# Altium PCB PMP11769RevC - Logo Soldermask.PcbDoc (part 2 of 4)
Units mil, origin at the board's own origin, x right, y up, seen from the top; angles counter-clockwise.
Board outline 7800 x 8510 mil, 4 copper layers (Top, Inner Top, Inner Bottom, Bottom), stack 33.235 mil thick; 451 components, 226 nets, 1199 pads, 1742 vias.
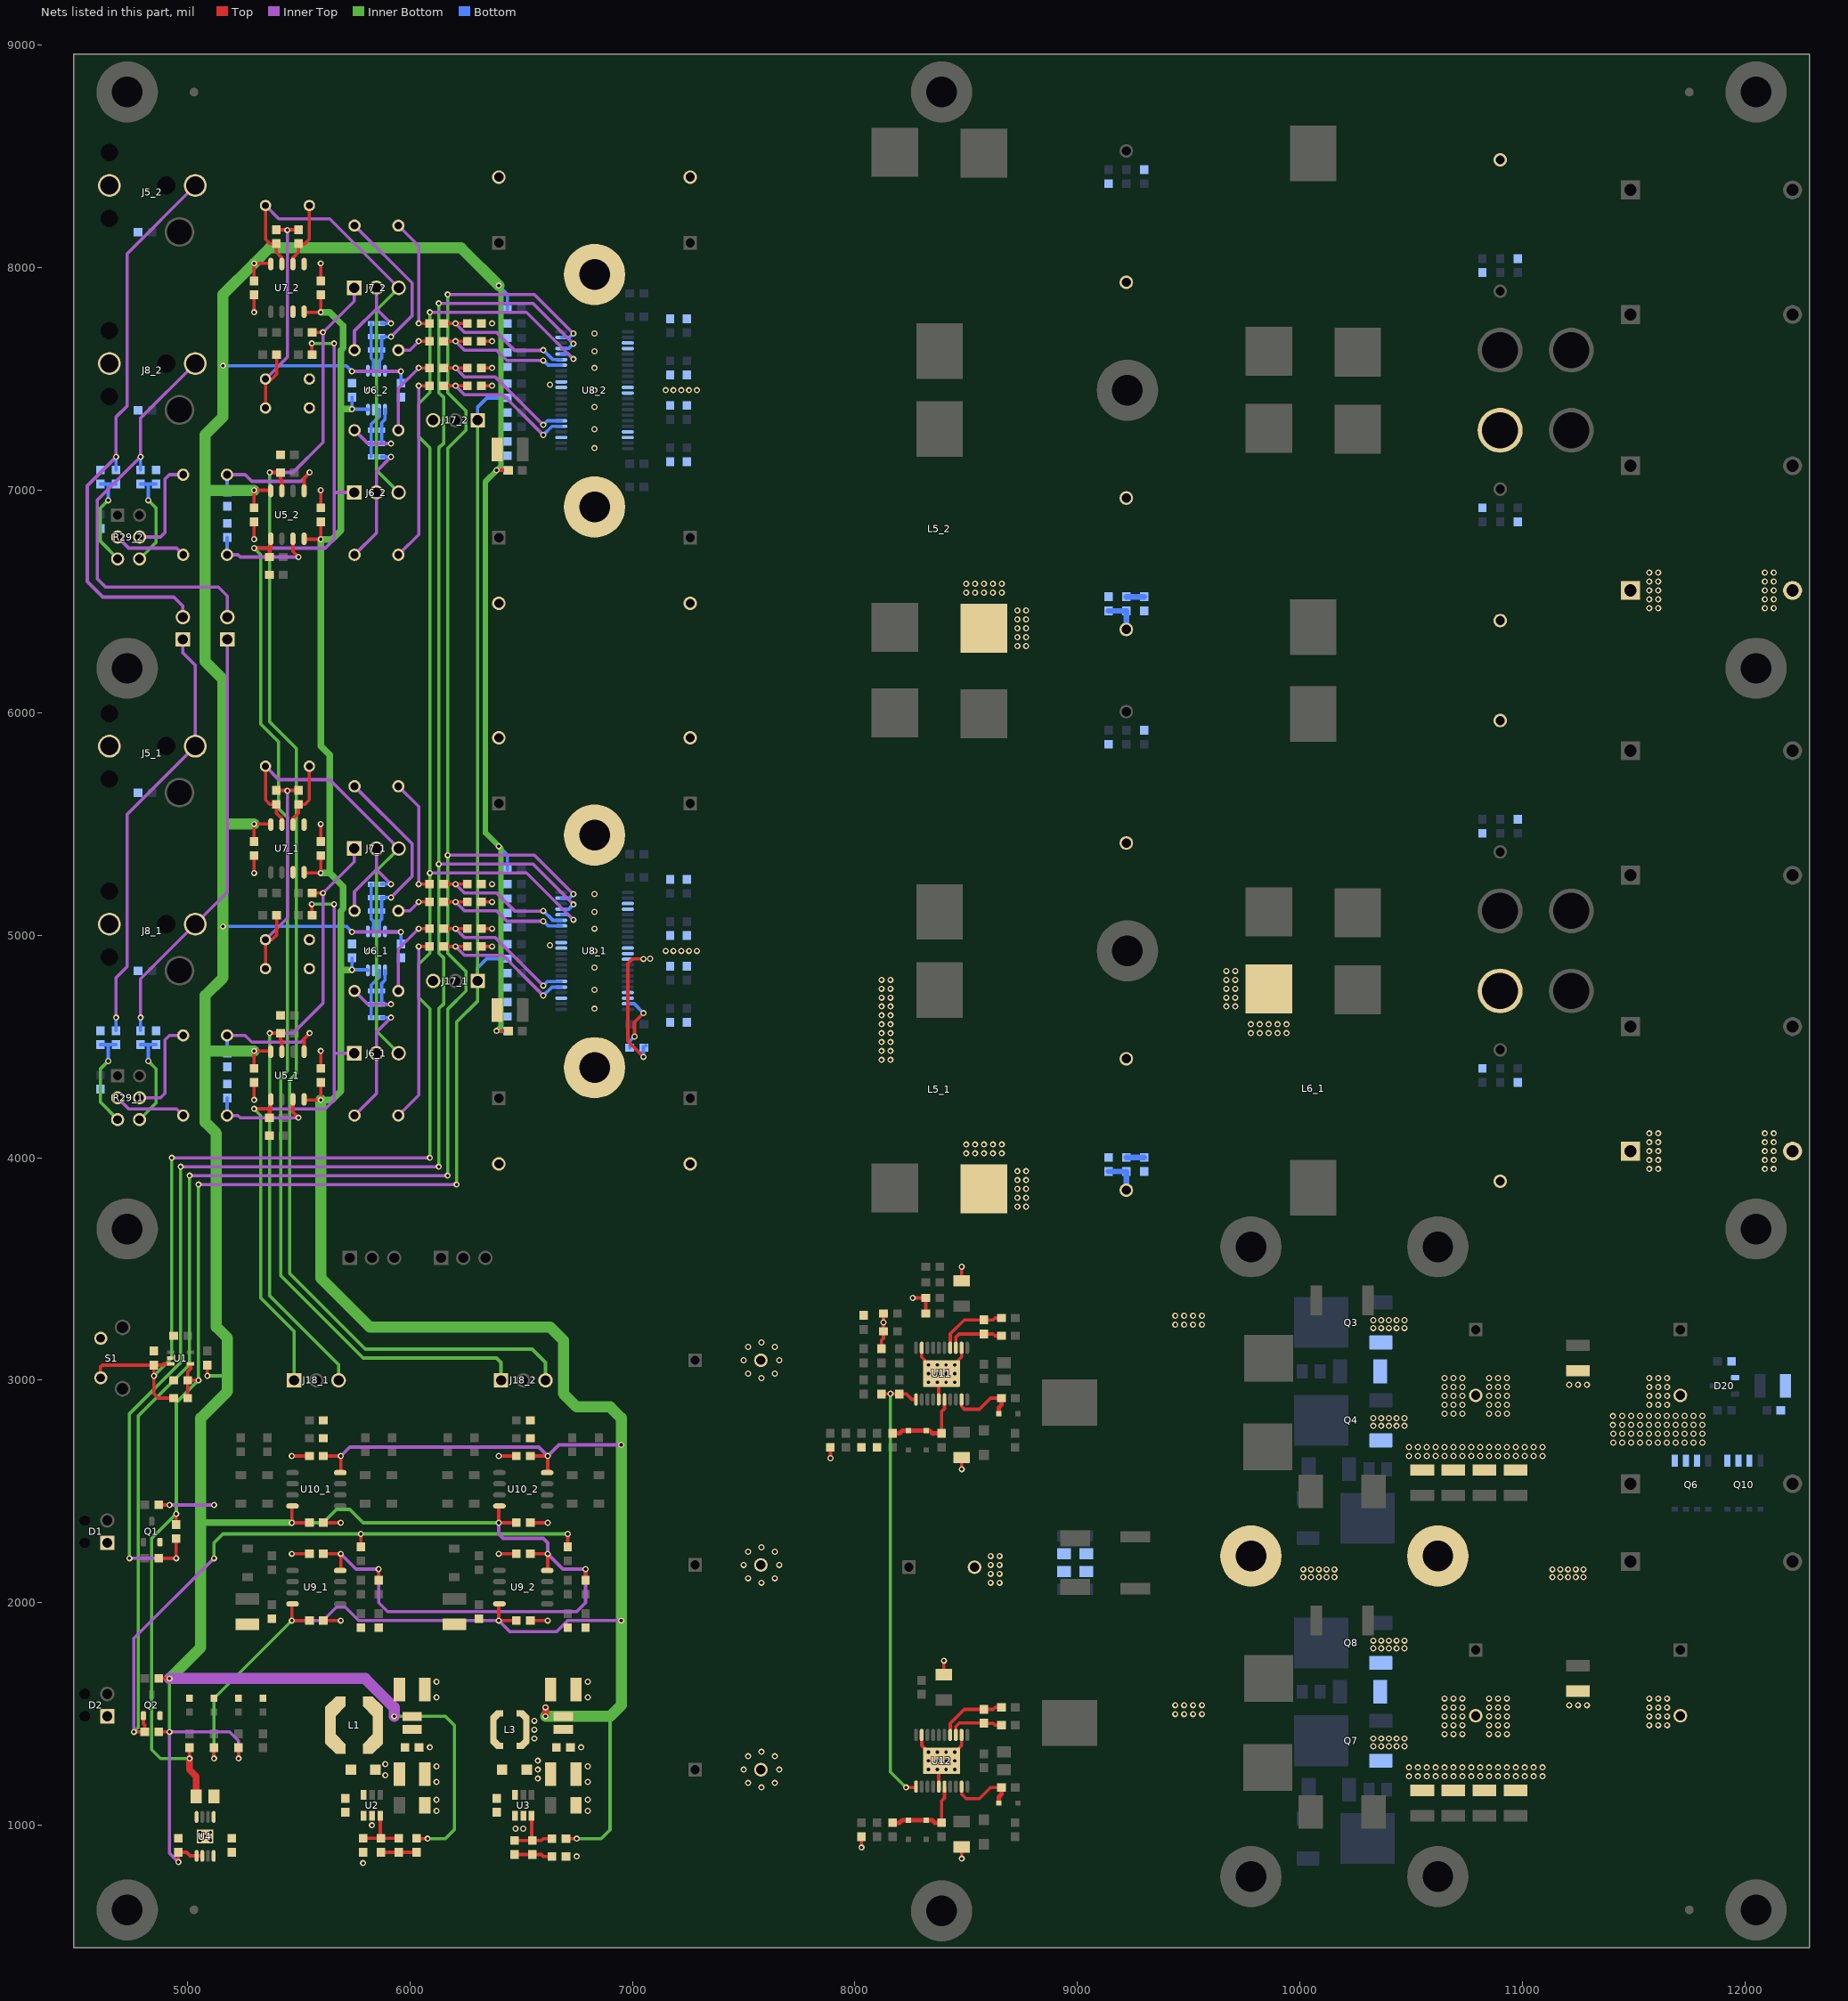
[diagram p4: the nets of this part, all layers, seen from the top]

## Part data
C1 C14 C58_1 C58_2 C59_1 C59_2 C71_1 C71_2: "CAP, CERM, 1 µF, 25 V, +/- 10%, X7R, 0603"
C2 C3 C7 C9 C12 C19_1 C19_2 C23_1 C23_2 C26_1 C26_2 C29_1 C29_2 C30_1 C30_2 C36_1 C36_2 C60_1 C60_2 C66_1 C66_2 C72_1 C72_2 C73_1 C73_2 C77_1 C77_2 C78_1 C78_2 C80_1 C80_2 C81_1 C81_2 C82_1 C82_2 C104 C106: "CAP, CERM, 0.1 µF, 50 V, +/- 10%, X7R, 0603"
C4 C13 C92 C93: "CAP, CERM, 1 µF, 50 V, +/- 10%, X7R, 1206"
C5 C6 C10 C11 C67_1 C67_2 C79_1 C79_2: "CAP, CERM, 10 µF, 25 V, +/- 20%, X7R, 1210"
C8 C17: "CAP, CERM, 220 pF, 50 V, +/- 5%, C0G/NP0, 0603"
C15: "CAP, CERM, 4.7 µF, 10 V, +/- 20%, X7R, 0805"
C16 C90: "CAP, CERM, 1000 pF, 50 V, +/- 10%, X7R, 0603"
C18_1 C18_2 C22_1 C22_2 C25_1 C25_2 C32_1 C32_2 C35_1 C35_2 C39_1 C39_2: "CAP, Film, 4.7 µF, 50 V, +/- 5%, TH"
C20_1 C20_2 C31_1 C31_2: "CAP, CERM, 22 pF, 50 V, +/- 5%, C0G/NP0, 0402"
C21_1 C21_2 C24_1 C24_2 C28_1 C28_2 C37_1 C37_2 C38_1 C38_2 C40_1 C40_2 C91: "CAP, CERM, 100 pF, 50 V, +/- 5%, C0G/NP0, 0603"
C27_1 C27_2: "CAP, Film, 0.1 µF, 63 V, +/- 5%, TH"
C33_1 C33_2: "CAP, Film, 0.22 µF, 63 V, +/- 5%, TH"
C34_1 C34_2: "CAP, Film, 0.15 µF, 63 V, +/- 5%, TH"
C41_1 C41_2 C61_1 C61_2 C68_1 C68_2 C74_1 C74_2: "CAP, CERM, 0.01 µF, 50 V, +/- 10%, X7R, 0603"
C42_1 C42_2 C43_1 C43_2 C44_1 C44_2 C45_1 C45_2 C109 C110 C113 C114: "CAP, AL, 820 µF, 50 V, +/- 20%, 0.042 ohm, TH"
C46_1 C46_2 C47_1 C47_2 C48_1 C48_2 C49_1 C49_2 C50_1 C50_2 C51_1 C51_2 C52_1 C52_2 C53_1 C53_2: "CAP, CERM, 1 µF, 50 V, +/- 10%, X7R, 0603"
C54_1 C54_2 C55_1 C55_2 C64_1 C64_2 C65_1 C65_2: "CAP, CERM, 0.033 µF, 50 V, +/- 10%, X7R, 0603"
C56_1 C56_2 C62_1 C62_2 C69_1 C69_2 C75_1 C75_2: "CAP, Film, 1 µF, 250 V, +/- 5%, TH"
C57_1 C57_2 C63_1 C63_2 C70_1 C70_2 C76_1 C76_2: "CAP, CERM, 1000 pF, 100 V, +/- 5%, C0G/NP0, 0603"
C83 C84: "CAP, CERM, 220 pF, 50 V, +/- 10%, X7R, 0603"
C85: "CAP, CERM, 0.047 µF, 50 V, +/- 10%, X7R, 0603"
C86 C87: "CAP, CERM, 4.7 µF, 16 V, +/- 20%, X7R, 1206"
C88 C89: "CAP, CERM, 0.22 µF, 25 V, +/- 10%, X7R, 0805"
C94: "CAP, CERM, 2.2 µF, 6.3 V, +/- 10%, X7R, AEC-Q200 Grade 1, 0603"
C95 C96 C111 C112 C115 C116: "CAP, CERM, 1000 pF, 100 V, +/- 20%, X7R, 0805"
C97 C99 C100 C102 C103 C105 C117 C119 C120 C122 C123: library part C3225X7R1H335M, "CAP, CERM, 4.7 µF, 50 V, +/- 15%, X7R, 1210"
C98 C101 C118 C121: "CAP, AL, 1800 µF, 35 V, +/- 20%, 0.028 ohm, TH"
C107 C108: "CAP, CERM, 0.1 µF, 100 V, +/- 10%, X7R, 0805"
D1 D2: library part 551-0403F, "LED, Yellow, TH"
D3 D8 D14 D15: library part PMEG6010CEH,115, "Diode, Schottky, 60 V, 1 A, SOD-123F"
D4 D5 D6 D7: "LED, Green, SMD"
D9_1 D9_2 D10_1 D10_2 D11_1 D11_2 D12_1 D12_2 D13_1 D13_2: library part 1N4148WFL-G3-08, "Diode, Switching, 100 V, 0.15 A, SOD-123FL"
D16 D21: library part SS36-E3/57T, "Diode, Schottky, 60 V, 3 A, SMC"
D17 D18 D19 D22 D23 D24: library part BAT54HT1G, "Diode, Schottky, 30 V, 0.2 A, SOD-323"
D20: "Diode, Zener, 15 V, 225 mW, SOT-23"
FID1 FID2 FID3 FID4: "Fiducial mark.  There is nothing to buy or mount."
J1 J3: "Header, 2.54 mm, 2x1, Gold, TH"
J2 J4 J6_1 J6_2 J7_1 J7_2 J17_1 J17_2 J18_1 J18_2: "Header, 2.54 mm, 3x1, Gold, TH"
J5_1 J5_2: "RCA Jack, Red, R/A, TH"
J8_1 J8_2: "RCA Jack, Black, R/A, TH"
J9_1 J9_2 J13_1 J13_2 J19: library part "973 582-101", "TEST SOCKET, PCB, 4MM, RED"
J10_1 J10_2 J11_1 J11_2 J14_1 J14_2 J15_1 J15_2: library part H3492-01, "Pin Receptacle, Dia 4 mm, Gold, TH"
J12_1 J12_2 J16_1 J16_2 J20: library part "973 582-100", "TEST SOCKET, PCB, 4MM, BLACK"
L1: "Inductor, Shielded Drum Core, Ferrite, 330 µH, 0.3 A, 1.2 ohm, SMD"
L2 L4: "Inductor, Shielded, Composite, 500 nH, 2.3 A, 0.04 ohm, SMD"
L3: "Inductor, Shielded Drum Core, Ferrite, 1 mH, 0.1 A, 21.5 ohm, SMD"
L5_1 L5_2 L6_1 L6_2 L7_1 L7_2 L8_1 L8_2 L9 L11: "Inductor, Shielded E Core, Ferrite, 10 µH, 28 A, 0.0026 ohm, SMD"
L10: library part IHLP2525AHERR10M01, "Inductor, Shielded, Ferrite, 100 nH, 18 A, 0.0035 ohm, SMD"
Q1 Q2: library part 2N7002E-T1-E3, "MOSFET, N-CH, 60 V, 0.24 A, SOT-23"
Q3 Q4 Q5 Q7 Q8 Q9: library part SUD50N10-18P, "MOSFET, N-CH, 60 V, 50 A, DPAK"
Q6 Q10: "MOSFET, N-CH, 30 V, 51 A, SON 5x6mm"
R1 R7: "RES, 47.5 k, 1%, 0.1 W, 0603"
R2 R8: "RES, 3.32 k, 1%, 0.1 W, 0603"
R3 R6 R25_1 R25_2 R30_1 R30_2 R43_1 R43_2 R53_1 R53_2 R55_1 R55_2 R56_1 R56_2 R59_1 R59_2 R61_1 R61_2 R63_1 R63_2 R64_1 R64_2 R65_1 R65_2 R66_1 R66_2: "RES, 10.0 k, 1%, 0.1 W, 0603"
R4 R19_1 R19_2 R20_1 R20_2 R26_1 R26_2 R36_1 R36_2 R37_1 R37_2 R42_1 R42_2: "RES, 100, 1%, 0.1 W, 0603"
R5: "RES, 80.6 k, 1%, 0.1 W, 0603"
R9 R17 R77: "RES, 49.9, 1%, 0.1 W, 0603"
R10 R16 R58_1 R58_2 R89 R91 R92 R100 R101: "RES, 1.00 k, 1%, 0.1 W, 0603"
R11 R18: "RES, 14.7 k, 1%, 0.1 W, 0603"
R12: "RES, 11.0 k, 1%, 0.1 W, 0603"
R13 R14: "RES, 2.94 k, 1%, 0.1 W, 0603"
R15: "RES, 200, 1%, 0.1 W, 0603"
R21_1 R21_2 R27_1 R27_2 R38_1 R38_2 R39_1 R39_2: "RES, 10.0 k, 1%, 0.063 W, 0402"
R22_1 R22_2: "RES, 13.7 k, 1%, 0.1 W, 0603"
R23_1 R23_2 R32_1 R32_2 R40_1 R40_2 R54_1 R54_2 R67 R70 R72 R73 R75 R76 R79 R83: "RES, 0, 5%, 0.1 W, 0603"
R24_1 R24_2 R41_1 R41_2 R74 R78: "RES, 100 k, 1%, 0.1 W, 0603"
R28_1 R28_2 R33_1 R33_2 R81 R84: "RES, 20.0 k, 1%, 0.1 W, 0603"
R29_1 R29_2: "Trimmer Potentiometer, 10K Ohm, 0.025W, TH"
R31_1 R31_2 R44_1 R44_2: "RES, 24.3 k, 1%, 0.1 W, 0603"
R34_1 R34_2: "RES, 4.53 k, 1%, 0.1 W, 0603"
R35_1 R35_2: "RES, 6.81 k, 1%, 0.1 W, 0603"
R45_1 R45_2 R46_1 R46_2 R47_1 R47_2 R48_1 R48_2 R50_1 R50_2 R51_1 R51_2 R52_1 R52_2 R69 R71: "RES, 3.32, 1%, 0.1 W, 0603"
R49_1 R49_2: "RES, 22.1 k, 1%, 0.1 W, 0603"
R57_1 R57_2: "RES, 23.7 k, 1%, 0.1 W, 0603"
R60_1 R60_2: "RES, 200 k, 1%, 0.1 W, 0603"
R62_1 R62_2: "RES, 365 k, 1%, 0.1 W, 0603"
R68: "RES, 30.1 k, 1%, 0.1 W, 0603"
R80: "RES, 7.68 k, 1%, 0.1 W, 0603"
R82: "RES, 37.4 k, 1%, 0.1 W, 0603"
R85: "RES, 3.74 k, 1%, 0.1 W, 0603"
R86: "RES, 44.2 k, 1%, 0.1 W, 0603"
R87 R90 R97 R99: "RES, 8.2, 5%, 0.75 W, 2010"
R88 R98: "RES, 0.0015, 1%, 1 W, 2512"
R93 R94 R95 R102 R103 R104: "RES, 4.75, 1%, 0.1 W, 0603"
R96: "RES, 0.68, 5%, 1 W, 2512"
S1: library part 1825027-2, "Switch, SPST-NO, Off-Mom, 0.05 A, 12 V, R/A, TH"
U1: library part TPS3803-01QDCKRQ1, "VOLTAGE DETECTOR, DCK0005A"
U2 U3: library part LM2841XMK-ADJL, "300 mA/600 mA up to 42V Input Step-Down DC/DC Regulator, 6-pin Tiny SOT23"
U4: library part TPS7A6633QDGNRQ1, "High-Voltage Ultralow-Iq Low-Dropout Regulator, DGN0008D"
U5_1 U5_2 U7_1 U7_2: library part OPA1662AIDRQ1, "Automotive Catalog, Sound Plus, Low-Power, Low-Noise and Distortion, Audio Operational Amplifier, 3 to 36 V, -40 to 85 degC, 8-pin SOIC (D0008A), Green (RoHS & no Sb/Br)"
U6_1 U6_2: "Automotive Catalog, Sound Plus, Low-Power, Low-Noise and Distortion, Audio Operational Amplifier, 3 to 36 V, -40 to 85 degC, 8-pin SOP (DGK0008A), Green (RoHS & no Sb/Br)"
U8_1 U8_2: library part TPA3251D2DDVR, "150W Stereo/300W MONO PurePath HD Analog-input Power Stage, DDV0044D"
U9_1 U9_2 U10_1 U10_2: library part LM2904QDRQ1, "Automotive Dual Low Power Op Amp, D0008A"
U11 U12: library part LM5122QMHX/NOPB, "Wide Input Synchronous Boost Controller with Multiple Phase Capability, PWP0020A"

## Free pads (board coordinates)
  round 275.59 hole 137.8 unplated: 0(4730,620) 0(4730,3680) 0(4730,6200) 0(4730,8790) 0(8390,615) 0(8390,8790) 0(9225,4930) 0(9225,7450) 0(9780,770) 0(9780,3600) 0(10620,770) 0(10620,3600) 0(12050,620) 0(12050,3680) 0(12050,6200) 0(12050,8790)
  round 275.59 hole 137.8: 0(6830,4405) 0(6830,5450) 0(6830,6925) 0(6830,7970) 0(9780,2210) 0(10620,2210)

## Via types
v1: diameter 28, hole 15, Top to Bottom, 1742 vias

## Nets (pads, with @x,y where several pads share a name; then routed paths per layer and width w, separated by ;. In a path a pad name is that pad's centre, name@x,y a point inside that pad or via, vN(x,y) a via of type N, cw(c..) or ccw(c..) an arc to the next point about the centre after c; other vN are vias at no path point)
+3V3: C2.2 C15.1 J17_1.1 J17_2.1 R1.2 R3.2 R15.2 R54_1.1 R54_2.1 U1.4 U4.8 | length 8355.1
  Top w15: R1.2@4950,2351.5 v1(4950,2400) ; R3.2@5001.5,2920 C2.2@5001.5,3000 ; v1(5010,1300) R15.2@5010,1348.5 ; U1.4@5014.29,3074.41 5014.29,3051.14 5001.5,3038.35 C2.2@5001.5,3000 ; v1(5050,3000) C2.2@5001.5,3000
  Top w30: v1(5010,1300) 5010,1250 5040,1220 C15.1@5040,1130
  Inner Top w15: v1(5050,3880) v1(6210,3880)
  Inner Bottom w15: v1(5010,1300) 4880,1300 4840,1340 4840,2290 v1(4950,2400) 4950.37,2400.37 4950.37,2900.37 v1(5050,3000) v1(5050,3880) ; v1(6210,3880) 6210,4610 6305,4705 J17_1.1@6305,4795 J17_2.1@6305,7315
  Bottom w15: J17_1.1@6305,4795 6305,4854.49 6345.51,4895 R54_1.1@6438.5,4895 ; J17_2.1@6305,7315 6305,7374.49 6345.51,7415 R54_2.1@6438.5,7415
+12V: C6.1 C14.1 C23_1.1 C23_2.1 C26_1.1 C26_2.1 C29_1.1 C29_2.1 C77_1.1 C77_2.1 C78_1.1 C78_2.1 L2.2 R2.2 R5.2 R7.2 R8.2 R9.2 R13.2 R46_1.2 R46_2.2 R48_1.2 R48_2.2 R51_1.2 R51_2.2 R57_1.2 R57_2.2 U4.1 U4.2 U5_1.8 U5_2.8 U6_1.8 U6_2.8 U7_1.8 U7_2.8 U9_1.8 U9_2.8 U10_1.8 U10_2.8 | length 22962.4
  Top w15: R7.2@4871.5,1420 v1(4920,1420) ; R8.2@4871.5,1660 v1(4920,1660) ; R2.2@4871.5,2440 v1(4920,2440) ; v1(4960,835) C14.1@4960,878.5 4996.5,878.5 5012.6,862.4 U4.1@5041.61,862.4 U4.2@5067.2,862.4 ; v1(5090,3020) R5.2@5090,3068.5 ; v1(5230,1300) R13.2@5230,1348.5 ; C26_1.1@5300,4401.5 v1(5300,4480) 5372.28,4480 U5_1.8@5375,4477.28 ; C29_1.1@5300,5421.5 v1(5300,5500) 5372.28,5500 U7_1.8@5375,5497.28 ; C26_2.1@5300,6921.5 v1(5300,7000) 5372.28,7000 U5_2.8@5375,6997.28 ; C29_2.1@5300,7941.5 v1(5300,8020) 5372.28,8020 U7_2.8@5375,8017.28 ; U10_1.8@5472.72,2435 5470,2432.28 v1(5470,2360) C78_1.1@5548.5,2360 ; C77_1.1@5611.5,2220 v1(5690,2220) 5690,2147.72 U9_1.8@5687.28,2145 ; R57_1.2@5860,2101.5 v1(5860,2151.67) ; R9.2@6030,941.5 6031.5,940 v1(6080,940) ; v1(6390,4570) R48_1.2@6443.5,4570 ; v1(6390,7090) R48_2.2@6443.5,7090 ; U10_2.8@6402.72,2435 6400,2432.28 v1(6400,2360) C78_2.1@6478.5,2360 ; C77_2.1@6541.5,2220 v1(6620,2220) 6620,2147.72 U9_2.8@6617.28,2145 ; R57_2.2@6790,2101.5 v1(6790,2151.67)
  Inner Top w15: v1(4920,2440) v1(5120,2440) ; v1(4960,835) 4920,875 v1(4920,1420) 5190,1420 5230,1380 v1(5230,1300) ; v1(5690,2220) 5758.33,2151.67 v1(5860,2151.67) 5860,2000 5900,1960 6750,1960 6790,2000 v1(6790,2151.67) 6688.33,2151.67 v1(6620,2220) 6620,2270 6600,2290 6420,2290 6400,2310 v1(6400,2360) ; v1(5740,5015) v1(5960,5015) ; v1(5740,7535) v1(5960,7535)
  Inner Top w50: v1(4920,1660) 5800,1660 5930,1530 v1(5930,1490)
  Inner Bottom w15: v1(4920,1420) v1(4920,1660) ; 5060,2440 v1(5120,2440) ; v1(5090,3020) 5170,3020 5180,3030 ; v1(5470,2360) 5610,2360 5670,2420 5730,2420 5790,2360 v1(6400,2360) ; v1(5930,1490) 6160,1490 6200,1450 6200,980 6160,940 v1(6080,940)
  Inner Bottom w25: v1(6390,4570) 6410.02,4590.02 6410.02,5389.98 v1(6400,5400) 6340,5460 6339.63,5460 6339.63,7039.63 v1(6390,7090) 6410.02,7110.02 6410.02,7909.98 v1(6400,7920)
  Inner Bottom w30: 5060,2360 v1(5470,2360)
  Inner Bottom w50: v1(4920,1660) 5060,1800 5060,2360 5060,2440 5060,2830 5180,2950 5180,3030 5180,3190 5130,3240 5130,4110 5080,4160 5080,4480 ; v1(5300,4480) 5080,4480 ; v1(5300,5500) 5160,5500 ; v1(5300,7000) 5080,7000 ; v1(6400,7920) 6230,8090 5370,8090 v1(5300,8020) 5160,7880 v1(5160,7560) 5160,7330 5080,7250 5080,7000 ; 5080,4480 5080,4730 5160,4810 5160,5500 ; 5080,7000 5080,6230 5160,6150 5160,5500
  Bottom w15: v1(5160,5040) 5715,5040 v1(5740,5015) ; v1(5160,7560) 5715,7560 v1(5740,7535) ; U6_1.8@5888.39,5017.6 5890.98,5015 v1(5960,5015) C23_1.1@5960,4961.5 ; U6_2.8@5888.39,7537.6 5890.98,7535 v1(5960,7535) C23_2.1@5960,7481.5 ; v1(6390,4570) R46_1.2@6438.5,4570 ; v1(6390,7090) R46_2.2@6438.5,7090 ; v1(6400,5400) 6438.5,5361.5 R51_1.2@6438.5,5295 ; v1(6400,7920) 6438.5,7881.5 R51_2.2@6438.5,7815
-12V: C11.2 C19_1.1 C19_2.1 C30_1.1 C30_2.1 C36_1.1 C36_2.1 C80_1.1 C80_2.1 C82_1.1 C82_2.1 L4.2 R14.2 R16.2 U5_1.4 U5_2.4 U6_1.4 U6_2.4 U7_1.4 U7_2.4 U9_1.4 U9_2.4 U10_1.4 U10_2.4 | length 14081.9
  Top w15: v1(5120,1300) R14.2@5120,1348.5 ; U9_1.4@5472.72,1995 5470,1992.28 v1(5470,1920) C80_1.1@5548.5,1920 ; U5_1.4@5525,4262.72 5527.72,4260 v1(5600,4260) C19_1.1@5600,4338.5 ; U7_1.4@5525,5282.72 5527.72,5280 v1(5600,5280) C36_1.1@5600,5358.5 ; U5_2.4@5525,6782.72 5527.72,6780 v1(5600,6780) C19_2.1@5600,6858.5 ; U7_2.4@5525,7802.72 5527.72,7800 v1(5600,7800) C36_2.1@5600,7878.5 ; C82_1.1@5611.5,2660 v1(5690,2660) 5690,2587.72 U10_1.4@5687.28,2585 ; U9_2.4@6402.72,1995 6400,1992.28 v1(6400,1920) C80_2.1@6478.5,1920 ; C82_2.1@6541.5,2660 v1(6620,2660) 6620,2587.72 U10_2.4@6617.28,2585 ; R16.2@6701.5,940 v1(6750,940)
  Top w30: v1(6610,1490) v1(6610,1530)
  Inner Top w15: v1(5470,1920) 5610,1920 5670,1980 5710,1980 5770,1920 v1(6400,1920) 6450,1870 6660,1870 6710,1920 v1(6950,1920) ; v1(5690,2660) 5730,2700 6580,2700 v1(6620,2660) 6670,2710 v1(6950,2710)
  Inner Bottom w15: v1(5120,1300) 5120,1570 v1(5470,1920) ; v1(6750,940) 6860,940 6900,980 6900,1485 6895,1490
  Inner Bottom w30: v1(5600,4260) 5650,4260 5690,4300 5690,4845 ; v1(5600,5280) 5640,5280 ; v1(5600,7800) 5640,7800 5701.14,7738.86 5701.14,7640 5690,7628.86 5690,7365 ; v1(5740,4845) 5690,4845 ; v1(5740,7365) 5690,7365 ; 5640,5280 5701.14,5218.86 5701.14,5120 5690,5108.86 5690,4845 ; 5640,5280 5640,5810 5600,5850 v1(5600,6780) 5650,6780 5690,6820 5690,7365
  Inner Bottom w50: v1(5600,4260) 5600,3460 5820,3240 6630,3240 6690,3180 6690,2940 6750,2880 6900,2880 6950,2830 v1(6950,2710) v1(6950,1920) 6950,1540 6900,1490 ; v1(6610,1490) 6895,1490
  Bottom w15: C30_1.1@5740,4898.5 v1(5740,4845) 5809.02,4845 U6_1.4@5811.61,4842.4 ; C30_2.1@5740,7418.5 v1(5740,7365) 5809.02,7365 U6_2.4@5811.61,7362.4
/CLIP_1: Q2.1 R7.1 R58_1.2 R58_2.2 U8_1.21 U8_2.21 | length 12109.8
  Top w15: v1(4760,1420) R7.1@4808.5,1420 4808.5,1451.5 4802.6,1457.4 Q2.1@4802.6,1492.76 Q2.1@4799.84,1490 ; R58_1.2@5780,2251.5 v1(5780,2310) ; R58_2.2@6710,2251.5 v1(6710,2310)
  Inner Top w15: v1(4760,1420) 4760,1840 v1(5120,2200) ; v1(5010,3920) v1(6170,3920) ; v1(6170,5360) 6560,5360 v1(6735,5185) ; v1(6170,7880) 6560,7880 v1(6735,7705)
  Inner Bottom w15: v1(4760,1420) 4780,1440 4780,2840 5010,3070 v1(5010,3920) ; v1(5120,2200) 5120,2270 5160,2310 v1(5780,2310) v1(6710,2310) ; v1(6170,3920) 6170,4667.15 6252.85,4750 6252.85,4837.15 6170,4920 v1(6170,5360) 6170,7187.15 6252.85,7270 6252.85,7357.15 6170,7440 v1(6170,7880)
  Bottom w15: U8_1.21@6680.39,5167.5 6717.5,5167.5 v1(6735,5185) ; U8_2.21@6680.39,7687.5 6717.5,7687.5 v1(6735,7705)
/FAULT_1: R1.1 R4.1 U8_1.19 U8_2.19 | length 8797.1
  Top w15: R4.1@4871.5,2200 v1(4950,2200) R1.1@4950,2288.5
  Inner Top w15: v1(4740,2200) v1(4950,2200) ; v1(4970,3960) v1(6130,3960) ; v1(6130,5320) 6553.7,5320 v1(6735,5138.7) ; v1(6130,7840) 6553.7,7840 v1(6735,7658.7)
  Inner Bottom w15: v1(4740,2200) 4740,2850 4970,3080 v1(4970,3960) ; v1(6130,3960) 6130,4670 6152.85,4692.85 6152.85,4897.15 6130,4920 v1(6130,5320) 6130,7190 6152.85,7212.85 6152.85,7417.15 6130,7440 v1(6130,7840)
  Bottom w15: U8_1.19@6680.39,5117.5 6713.8,5117.5 v1(6735,5138.7) ; U8_2.19@6680.39,7637.5 6713.8,7637.5 v1(6735,7658.7)
/RESET_1: C1.1 R3.1 S1.2 U1.3 U8_1.18 U8_2.18 | length 8243.8
  Top w15: S1.2@4610.98,3011.42 4610,3012.4 4610,3060 4618.5,3068.5 C1.1@4850,3068.5 ; U1.3@4925.71,3074.41 4894.41,3074.41 4888.5,3068.5 C1.1@4850,3068.5 ; R3.1@4938.5,2920 4870,2920 4850,2940 v1(4850,3020) C1.1@4850,3068.5
  Inner Top w15: v1(4930,4000) v1(6090,4000) ; v1(6090,5280) 6525,5280 v1(6735,5070) ; v1(6090,7800) 6525,7800 v1(6735,7590)
  Inner Bottom w15: v1(4850,3020) 4930,3100 v1(4930,4000) ; v1(6090,4000) 6090,4670 6040,4720 6040,4870 6090,4920 v1(6090,5280) 6090,7190 6040,7240 6040,7390 6090,7440 v1(6090,7800)
  Bottom w15: U8_1.18@6680.39,5092.5 6712.5,5092.5 v1(6735,5070) ; U8_2.18@6680.39,7612.5 6712.5,7612.5 v1(6735,7590)
BUFF_L1: J6_1.1 J18_1.1 R28_1.1 R31_1.2 U5_1.1 | length 2958.1
  Top w15: v1(5300,4220) 5370,4220 5375,4215 ; R31_1.2@5368.5,4180 5368.5,4208.5 5375,4215 ; U5_1.1@5372.28,4260 U5_1.1@5375,4262.72 5375,4215 ; v1(5560,5140) 5560,5091.5 R28_1.1@5561.5,5090
  Inner Top w15: v1(5300,4220) 5620,4220 5660,4260 5660,4470 ; v1(5660,5140) 5660,4470 ; J6_1.1@5750,4470 5660,4470
  Inner Bottom w15: v1(5300,4220) 5330,4190 5330,3370 5480,3220 J18_1.1@5480,3000 ; v1(5560,5140) v1(5660,5140)
BUFF_L2: J6_2.1 J18_2.1 R28_2.1 R31_2.2 U5_2.1 | length 6239.6
  Top w15: v1(5300,6740) 5370,6740 5375,6735 ; R31_2.2@5368.5,6700 5368.5,6728.5 5375,6735 ; U5_2.1@5372.28,6780 U5_2.1@5375,6782.72 5375,6735 ; v1(5560,7660) 5560,7611.5 R28_2.1@5561.5,7610
  Inner Top w15: v1(5300,6740) 5620,6740 5660,6780 5660,6990 ; v1(5660,7660) 5660,6990 ; J6_2.1@5750,6990 5660,6990
  Inner Bottom w15: v1(5300,6740) 5330,6710 5330,5950 5410,5870 5410,5570 5450,5530 5450,4390 5420,4360 5420,3470 5790,3100 6390,3100 6410,3080 J18_2.1@6410,3000 ; v1(5560,7660) v1(5660,7660)
BUFF_R1: J7_1.1 J18_1.3 R33_1.1 R44_1.2 U5_1.7 | length 2919.4
  Top w15: v1(5370,4560) R44_1.2@5418.5,4560 5418.5,4531.5 5425,4525 U5_1.7@5425,4477.28 ; R33_1.1@5561.5,5190 v1(5610,5190)
  Inner Top w15: v1(5370,4560) 5474.45,4560 5610,4695.55 v1(5610,5190) 5750,5330 J7_1.1@5750,5390
  Inner Bottom w15: v1(5370,4560) 5370,3380 5680,3070 J18_1.3@5680,3000
BUFF_R2: J7_2.1 J18_2.3 R33_2.1 R44_2.2 U5_2.7 | length 6288.8
  Top w15: v1(5370,7080) R44_2.2@5418.5,7080 5418.5,7051.5 5425,7045 U5_2.7@5425,6997.28 ; R33_2.1@5561.5,7710 v1(5610,7710)
  Inner Top w15: v1(5370,7080) 5474.45,7080 5610,7215.55 v1(5610,7710) 5750,7850 J7_2.1@5750,7910
  Inner Bottom w15: v1(5370,7080) 5370,5960 5490,5840 5490,4380 5460,4350 5460,3480 5800,3140 6550,3140 6610,3080 J18_2.3@6610,3000
COMP: C85.1 C90.1 U11.11 U12.11 | length 2010.5
  Top w15: C90.1@8120,2938.5 C85.1@8200,2938.5 8231.5,2938.5 8256.14,2913.86 U11.11@8274.84,2913.86 ; v1(8230,1170) 8270.98,1170 U12.11@8274.84,1173.86
  Inner Bottom w15: v1(8160,2940) 8160,1240 v1(8230,1170)
CSN-1: C83.2 R92.1 U11.3 | length 262.2
  Top w15: U11.3@8453.98,3146.14 8453.98,3193.35 8453.66,3193.66 8468.5,3208.5 C83.2@8580,3208.5 8621.5,3208.5 8630,3200 R92.1@8658.5,3200
CSN-2: C84.2 R101.1 U12.3 | length 253.1
  Top w15: U12.3@8453.98,1406.14 8453.98,1443.98 8470,1460 8578.5,1460 C84.2@8580,1458.5 8621.5,1458.5 8630,1450 R101.1@8658.5,1450
CSP-1: C83.1 R91.1 U11.4 | length 322.3
  Top w15: U11.4@8428.39,3146.14 8428.39,3207.76 8428.07,3208.07 8491.5,3271.5 C83.1@8580,3271.5 8621.5,3271.5 8630,3280 R91.1@8658.5,3280
CSP-2: C84.1 R100.1 U12.4 | length 312
  Top w15: U12.4@8428.39,1406.14 8428.39,1458.39 8491.5,1521.5 C84.1@8580,1521.5 8621.5,1521.5 8630,1530 R100.1@8658.5,1530
GND: C1.2 C2.1 C4.2 C5.2 C6.2 C7.1 C10.1 C11.1 C12.2 C13.2 C14.2 C15.2 C16.2 C19_1.2 C19_2.2 C21_1.2 C21_2.2 C23_1.2 C23_2.2 C24_1.2 C24_2.2 C26_1.2 C26_2.2 C28_1.2 C28_2.2 C29_1.2 C29_2.2 C30_1.2 C30_2.2 C33_1.2 C33_2.2 C34_1.2 C34_2.2 C36_1.2 C36_2.2 C37_1.2 C37_2.2 C38_1.2 C38_2.2 C40_1.2 C40_2.2 C42_1.2 C42_2.2 C43_1.2 C43_2.2 C44_1.2 C44_2.2 C45_1.2 C45_2.2 C46_1.2 C46_2.2 C47_1.2 C47_2.2 C48_1.2 C48_2.2 C49_1.2 C49_2.2 C50_1.2 C50_2.2 C51_1.2 C51_2.2 C52_1.2 C52_2.2 C53_1.2 C53_2.2 C56_1.2 C56_2.2 C57_1.2 C57_2.2 C58_1.2 C58_2.2 C59_1.2 C59_2.2 C60_1.1 C60_2.1 C62_1.2 C62_2.2 C63_1.2 C63_2.2 C66_1.1 C66_2.1 C67_1.2 C67_2.2 C69_1.2 C69_2.2 C70_1.2 C70_2.2 C71_1.1 C71_2.1 C72_1.1 C72_2.1 C73_1.2 C73_2.2 C75_1.2 C75_2.2 C76_1.2 C76_2.2 C77_1.2 C77_2.2 C78_1.2 C78_2.2 C79_1.2 C79_2.2 C80_1.2 C80_2.2 C81_1.1 C81_2.1 C82_1.2 C82_2.2 C86.2 C87.2 C91.2 C92.1 C93.1 C94.2 C97.2 C98.2 C99.2 C100.2 C101.2 C102.2 C103.2 C104.2 C105.2 C106.1 C107.1 C108.2 C109.2 C110.2 C112.2 C113.2 C114.2 C115.1 C117.2 C118.2 C119.2 C120.2 C121.2 C122.2 C123.2 D1.1 D2.1 D3.2 D4.1 D5.1 D6.2 D7.1 D20.1 J5_1.1 J5_2.1 J8_1.1 J8_2.1 J17_1.3 J17_2.3 L3.2 pad.0@6830,4405 pad.0@6830,5450 pad.0@6830,6925 pad.0@6830,7970 pad.0@9780,2210 pad.0@10620,2210 Q1.2 Q2.2 Q3.3 Q4.3 Q6.1 Q6.2 Q6.3 Q7.3 Q8.3 Q10.1 Q10.2 Q10.3 R6.1 R10.1 R17.1 R23_1.1 R23_2.1 R24_1.1 R24_2.1 R30_1.2 R30_2.2 R32_1.1 R32_2.1 R40_1.1 R40_2.1 R41_1.1 R41_2.1 R43_1.2 R43_2.2 R45_1.1 R45_2.1 R47_1.1 R47_2.1 R49_1.1 R49_2.1 R50_1.1 R50_2.1 R52_1.1 R52_2.1 R53_1.1 R53_2.1 R60_1.1 R60_2.1 R61_1.2 R61_2.2 R65_1.1 R65_2.1 R66_1.1 R66_2.1 R79.2 R80.1 R81.1 R82.1 R83.1 R84.1 R85.1 R86.1 R90.1 R99.1 S1.1 U1.2 U2.2 U4.5 U4.9 U6_1.3 U6_1.5 U6_2.3 U6_2.5 U7_1.3 U7_1.5 U7_2.3 U7_2.5 U8_1.3 U8_1.12 U8_1.13 U8_1.25 U8_1.26 U8_1.33 U8_1.34 U8_1.41 U8_1.42 U8_2.3 U8_2.12 U8_2.13 U8_2.25 U8_2.26 U8_2.33 U8_2.34 U8_2.41 U8_2.42 U11.2 U11.9 U11.15 U11.21 U12.2 U12.9 U12.15 U12.21 | length 3077.5
  Top w15: v1(5300,4260) C26_1.2@5300,4338.5 ; v1(5300,5280) C29_1.2@5300,5358.5 ; v1(5300,6780) C26_2.2@5300,6858.5 ; v1(5300,7800) C29_2.2@5300,7878.5 ; v1(5470,2220) C77_1.2@5548.5,2220 ; v1(5470,2660) C82_1.2@5548.5,2660 ; C19_1.2@5600,4401.5 v1(5600,4480) ; C36_1.2@5600,5421.5 v1(5600,5500) ; C19_2.2@5600,6921.5 v1(5600,7000) ; C36_2.2@5600,7941.5 v1(5600,8020) ; C80_1.2@5611.5,1920 v1(5690,1920) ; C78_1.2@5611.5,2360 v1(5690,2360) ; C21_1.2@6321.5,4948.7 6322.8,4950 v1(6370,4950) ; C28_1.2@6321.5,5028.7 6322.8,5030 v1(6370,5030) ; C40_1.2@6321.5,5148.7 6322.8,5150 v1(6370,5150) ; C21_2.2@6321.5,7468.7 6322.8,7470 v1(6370,7470) ; C28_2.2@6321.5,7548.7 6322.8,7550 v1(6370,7550) ; C40_2.2@6321.5,7668.7 6322.8,7670 v1(6370,7670) ; v1(6400,2220) C77_2.2@6478.5,2220 ; v1(6400,2660) C82_2.2@6478.5,2660 ; C80_2.2@6541.5,1920 v1(6620,1920) ; C78_2.2@6541.5,2360 v1(6620,2360) ; v1@7890,2651.5 R81.1@7890,2700 ; v1(8030,900) R84.1@8030,948.5 ; R85.1@8120,3141.5 8120,3180 8128.5,3188.5 v1(8128.5,3260) C94.2@8128.5,3300 ; v1(8260,3370) R80.1@8318.5,3370 C91.2@8318.5,3300 ; U11.9@8300.12,3155.51 8300,3155.39 8300,3105 8365.63,3039.37 U11.21@8389.68,3039.37 ; U12.9@8300.43,1406.14 8300.43,1359.57 8370,1290 v1(8370.32,1290) U12.21@8390,1290 ; U11.15@8376.89,2923.23 8376.89,3026.57 U11.21@8389.68,3039.37 ; U12.15@8377.2,1173.86 8377.2,1277.2 U12.21@8390,1290 ; C93.1@8400,1677.09 v1(8400,1740) ; U11.2@8479.25,3155.51 8480,3154.76 8480,3105 8414.37,3039.37 U11.21@8389.68,3039.37 ; U12.2@8479.57,1406.14 8479.57,1359.57 8410,1290 v1(8409.69,1290) U12.21@8390,1290 ; v1(8480,850) C87.2@8480,902.91 ; v1(8480,2600.55) C86.2@8480,2652.91 ; C92.1@8480,3447.09 v1(8480,3510)
  other v1: 5790,830 6750,860 5056.38,932.28 5103.62,932.28 5080,950 5056.38,967.72 5103.62,967.72 5830,1000 6120,1065 6800,1065 6120,1115 6800,1115 7580,1170 7520,1190 7640,1190 6120,1195 6800,1195 10490,1220 10530,1220 10570,1220 10610,1220 10650,1220 10690,1220 10730,1220 10770,1220 10810,1220 10850,1220 10890,1220 10930,1220 10970,1220 11010,1220 11050,1220 11090,1220 5890,1225 7500,1250 7660,1250 8330.94,1250.63 8370.32,1250.63 8409.69,1250.63 8449.06,1250.63 10490,1260 10530,1260 10570,1260 10610,1260 10650,1260 10690,1260 10730,1260 10770,1260 10810,1260 10850,1260 10890,1260 10930,1260 10970,1260 11010,1260 11050,1260 11090,1260 6120,1265 6800,1265 5890,1275 8330.94,1290 8449.06,1290 7520,1310 7640,1310 8330.94,1329.37 8370.32,1329.37 8409.69,1329.37 8449.06,1329.37 7580,1330 6090,1350 6770,1350 10330,1355 10365,1355 10400,1355 10435,1355 10470,1355 6560,1390 10330,1390 10365,1390 10400,1390 10435,1390 10470,1390 10650,1410 10690,1410 10730,1410 10850,1410 10890,1410 10930,1410 6560,1430 10650,1450 10690,1450 10730,1450 10850,1450 10890,1450 10930,1450 11570,1450 11610,1450 11650,1450 6560,1470 10650,1490 10690,1490 10730,1490 10850,1490 10890,1490 10930,1490 11570,1490 11610,1490 11650,1490 9440,1500 9480,1500 9520,1500 9560,1500 10650,1530 10690,1530 10730,1530 10850,1530 10890,1530 10930,1530 11570,1530 11610,1530 11650,1530 9440,1540 9480,1540 9520,1540 9560,1540 11210,1540 11250,1540 11290,1540 10650,1570 10690,1570 10730,1570 10850,1570 10890,1570 10930,1570 11570,1570 11610,1570 11650,1570 6120,1575 6800,1575 6120,1645 6800,1645 10330,1795 10365,1795 10400,1795 10435,1795 10470,1795 10330,1830 10365,1830 10400,1830 10435,1830 10470,1830 7580,2090 8610,2090 8650,2090 7520,2110 7640,2110 10015,2115 10050,2115 10085,2115 10120,2115 10155,2115 11135,2115 11170,2115 11205,2115 11240,2115 11275,2115 8610,2130 8650,2130 10015,2150 10050,2150 10085,2150 10120,2150 10155,2150 11135,2150 11170,2150 11205,2150 11240,2150 11275,2150 7500,2170 7660,2170 8610,2170 8650,2170 8610,2210 8650,2210 7520,2230 7640,2230 7580,2250 7890,2650 10490,2660 10530,2660 10570,2660 10610,2660 10650,2660 10690,2660 10730,2660 10770,2660 10810,2660 10850,2660 10890,2660 10930,2660 10970,2660 11010,2660 11050,2660 11090,2660 10490,2700 10530,2700 10570,2700 10610,2700 10650,2700 10690,2700 10730,2700 10770,2700 10810,2700 10850,2700 10890,2700 10930,2700 10970,2700 11010,2700 11050,2700 11090,2700 11408.5,2720 11448.5,2720 11488.5,2720 11528.5,2720 11568.5,2720 11608.5,2720 11648.5,2720 11688.5,2720 11728.5,2720 11768.5,2720 11808.5,2720 11408.5,2760 11448.5,2760 11488.5,2760 11528.5,2760 11568.5,2760 11608.5,2760 11648.5,2760 11688.5,2760 11728.5,2760 11768.5,2760 11808.5,2760 10330,2795 10365,2795 10400,2795 10435,2795 10470,2795 11406.95,2798.93 11448.5,2800 11488.5,2800 11528.5,2800 11568.5,2800 11608.5,2800 11648.5,2800 11688.5,2800 11728.5,2800 11768.5,2800 11808.5,2800 10330,2830 10365,2830 10400,2830 10435,2830 10470,2830 11406.95,2838.93 11448.5,2840 11488.5,2840 11528.5,2840 11568.5,2840 11608.5,2840 11648.5,2840 11688.5,2840 11728.5,2840 11768.5,2840 11808.5,2840 10650,2850 10690,2850 10730,2850 10850,2850 10890,2850 10930,2850 10650,2890 10690,2890 10730,2890 10850,2890 10890,2890 10930,2890 11570,2890 11610,2890 11650,2890 10650,2930 10690,2930 10730,2930 10850,2930 10890,2930 10930,2930 11570,2930 11610,2930 11650,2930 10650,2970 10690,2970 10730,2970 10850,2970 10890,2970 10930,2970 11570,2970 11610,2970 11650,2970 11210,2980 11250,2980 11290,2980 8330.94,2990.63 8370.32,2990.63 8409.69,2990.63 8449.06,2990.63 7580,3010 10650,3010 10690,3010 10730,3010 10850,3010 10890,3010 10930,3010 11570,3010 11610,3010 11650,3010 7520,3030 7640,3030 8330.94,3030 8370.32,3030 8409.69,3030 8449.06,3030 8330.94,3069.37 8370.32,3069.37 8409.69,3069.37 8449.06,3069.37 7500,3090 7660,3090 7520,3150 7640,3150 7580,3170 10330,3235 10365,3235 10400,3235 10435,3235 10470,3235 9440,3250 9480,3250 9520,3250 9560,3250 10330,3270 10365,3270 10400,3270 10435,3270 10470,3270 9440,3290 9480,3290 9520,3290 9560,3290 6830,4670 6830,4755 6830,4855 5815,4930 6830,4930 7150,4930 7185,4930 7220,4930 7255,4930 7290,4930 6630,4955 6830,5030 6830,5105 6830,5185 6370,5230 6830,7190 6830,7275 6830,7375 5815,7450 6830,7450 7150,7450 7185,7450 7220,7450 7255,7450 7290,7450 6630,7475 6830,7550 6830,7625 6830,7705 6370,7750
HO-1: D19.1 R95.1 U11.19 | length 312.8
  Top w15: U11.19@8480.93,2912.5 U11.19@8479.57,2913.86 8479.57,2882.78 8492.35,2870 8560,2870 8610,2920 R95.1@8658.5,2920
  Top w20: D19.1@8646.69,2850 8646.69,2877.19 8658.5,2889 R95.1@8658.5,2920
HO-2: D24.1 R104.1 U12.19 | length 316.4
  Top w15: U12.19@8479.57,1173.86 8479.57,1140.43 8500,1120 8560,1120 8610,1170 R104.1@8658.5,1170
  Top w20: D24.1@8646.69,1100 8646.69,1127.19 8658.5,1139 R104.1@8658.5,1170
IN_L1: J3.1 J5_1.3 R20_1.1 | length 1929
  Inner Top w15: v1(4680,4630) 4680,4810 4730,4860 4730,5544.17 J5_1.3@5035.83,5850 5035.83,6214.17 4980,6270 J3.1@4980,6330
  Bottom w15: R20_1.1@4680,4571.5 v1(4680,4630)
IN_L2: J3.2 J5_2.3 R20_2.1 | length 2565.3
  Inner Top w15: J3.2@4980,6430 4980,6480 4940,6520 4620,6520 4550,6590 4550,7020 v1(4680,7150) 4680,7330 4730,7380 4730,8064.17 J5_2.3@5035.83,8370
  Bottom w15: R20_2.1@4680,7091.5 v1(4680,7150)
IN_R1: J1.1 J8_1.3 R37_1.1 | length 1920
  Inner Top w15: v1(4790,4630) 4790,4804.17 J8_1.3@5035.83,5050 5180,5194.17 J1.1@5180,6330
  Bottom w15: R37_1.1@4790,4571.5 v1(4790,4630)
IN_R2: J1.2 J8_2.3 R37_2.1 | length 1920.4
  Inner Top w15: J8_2.3@5035.83,7570 4790,7324.17 v1(4790,7150) 4595,6955 4595,6602.99 4632.99,6565 5140,6565 5180,6525 J1.2@5180,6430
  Bottom w15: R37_2.1@4790,7091.5 v1(4790,7150)
INPUT_A_1: C21_1.1 R19_1.2 U8_1.5 | length 690.1
  Top w15: R19_1.2@6151.5,4950 v1(6205,4950) C21_1.1@6258.5,4950
  Inner Top w15: v1(6205,4950) 6245,4910 6418.7,4910 v1(6600,4728.7)
  Bottom w15: v1(6600,4728.7) 6638.8,4767.5 U8_1.5@6680.39,4767.5
INPUT_A_2: C21_2.1 R19_2.2 U8_2.5 | length 690.1
  Top w15: R19_2.2@6151.5,7470 v1(6205,7470) C21_2.1@6258.5,7470
  Inner Top w15: v1(6205,7470) 6245,7430 6418.7,7430 v1(6600,7248.7)
  Bottom w15: v1(6600,7248.7) 6638.8,7287.5 U8_2.5@6680.39,7287.5
INPUT_B_1: C28_1.1 R26_1.2 U8_1.6 | length 696.4
  Top w15: R26_1.2@6151.5,5030 v1(6205,5030) C28_1.1@6258.5,5030
  Inner Top w15: v1(6205,5030) 6245,4990 6383.7,4990 v1(6600,4773.7)
  Bottom w15: v1(6600,4773.7) 6618.8,4792.5 U8_1.6@6680.39,4792.5
INPUT_B_2: C28_2.1 R26_2.2 U8_2.6 | length 696.4
  Top w15: R26_2.2@6151.5,7550 v1(6205,7550) C28_2.1@6258.5,7550
  Inner Top w15: v1(6205,7550) 6245,7510 6383.7,7510 v1(6600,7293.7)
  Bottom w15: v1(6600,7293.7) 6618.8,7312.5 U8_2.6@6680.39,7312.5
INPUT_C_1: C40_1.1 R42_1.2 U8_1.16 | length 626.9
  Top w15: R42_1.2@6151.5,5150 v1(6205,5150) C40_1.1@6258.5,5150
  Inner Top w15: v1(6205,5150) 6245,5110 6390,5110 6436.3,5063.7 v1(6600,5063.7)
  Bottom w15: v1(6600,5063.7) 6621.2,5042.5 U8_1.16@6680.39,5042.5
INPUT_C_2: C40_2.1 R42_2.2 U8_2.16 | length 626.9
  Top w15: R42_2.2@6151.5,7670 v1(6205,7670) C40_2.1@6258.5,7670
  Inner Top w15: v1(6205,7670) 6245,7630 6390,7630 6436.3,7583.7 v1(6600,7583.7)
  Bottom w15: v1(6600,7583.7) 6621.2,7562.5 U8_2.16@6680.39,7562.5
INPUT_D_1: C37_1.1 R36_1.2 U8_1.17 | length 651
  Top w15: R36_1.2@6151.5,5230 v1(6205,5230) C37_1.1@6258.5,5230
  Inner Top w15: v1(6205,5230) 6245,5190 6390,5190 6471.3,5108.7 v1@6600,5108.7
  Bottom w15: v1(6600,5110) 6641.2,5068.8 6641.2,5067.5 U8_1.17@6680.39,5067.5
INPUT_D_2: C37_2.1 R36_2.2 U8_2.17 | length 651
  Top w15: R36_2.2@6151.5,7750 v1(6205,7750) C37_2.1@6258.5,7750
  Inner Top w15: v1(6205,7750) 6245,7710 6390,7710 6471.3,7628.7 v1@6600,7628.7
  Bottom w15: v1(6600,7630) 6641.2,7588.8 6641.2,7587.5 U8_2.17@6680.39,7587.5
LO-1: D17.1 D18.1 R93.1 R94.1 U11.16 | length 397.9
  Top w15: R93.1@8390,2761.5 8390,2860 8402.48,2872.48 U11.16@8402.48,2923.23
  Top w20: R94.1@8170,2761.5 8201,2761.5 8212.81,2773.31 D18.1@8240,2773.31 D17.1@8320,2773.31 8337.19,2773.31 8350.5,2760 8352,2761.5 R93.1@8390,2761.5
LO-2: D22.1 D23.1 R102.1 R103.1 U12.16 | length 397.4
  Top w15: R103.1@8390,1011.5 8390,1110 8402.8,1122.8 U12.16@8402.8,1173.86
  Top w20: R102.1@8170,1011.5 8201,1011.5 8212.81,1023.31 D22.1@8240,1023.31 D23.1@8320,1023.31 8347.19,1023.31 8359,1011.5 R103.1@8390,1011.5
NetC3_1: C3.1 D3.1 L1.1 U2.6
NetC3_2: C3.2 U2.1
NetC5_1: C5.1 C7.2 L1.2 L2.1
NetC8_1: C8.1 R9.1 R11.2 | length 160
  Top w15: R11.2@5870,878.5 R9.1@6030,878.5
NetC8_2: C8.2 R10.2 R11.1 U2.3 | length 255.4
  Top w15: R10.2@5790,941.5 C8.2@5950,941.5 ; U2.3@5867.4,1042.76 5867.4,949.76 R11.1@5869.13,948.03
NetC9_1: C9.1 D8.1 L3.1 U3.6
NetC9_2: C9.2 U3.1
NetC10_2: C10.2 C12.1 D8.2 L4.1 U3.2
  other v1: 6475,985 6510,985 6575,1210 6575,1250 6575,1290
NetC16_1: C16.1 U4.4
NetC17_1: C17.1 R17.2 R18.2 | length 172
  Top w15: R18.2@6470,868.5 C17.1@6550,868.5 6591.5,868.5 6600,860 R17.2@6638.5,860
NetC17_2: C17.2 R16.1 R18.1 U3.3 | length 274.4
  Top w15: R18.1@6470,931.5 C17.2@6550,931.5 ; C17.2@6547.4,934.09 C17.2@6550,931.5 ; C17.2@6547.4,944.09 U3.3@6547.4,1042.76 ; R16.1@6638.5,940 6600,940 6591.5,931.5 C17.2@6550,931.5
NetC18_1_1: C18_1.1 R19_1.1 | length 847
  Top w15: v1(6040,4950) 6087.2,4950 R19_1.1@6088.5,4948.7
  Inner Top w15: C18_1.1@5948.43,4190 6040,4281.57 v1(6040,4950)
NetC18_1_2: C18_1.2 J6_1.2 R27_1.1 | length 549.1
  Inner Top w15: C18_1.2@5751.57,4190 5850,4288.43 J6_1.2@5850,4470 5850,4565 v1(5915,4630)
  Bottom w15: R27_1.1@5873.62,4630 v1(5915,4630)
NetC18_2_1: C18_2.1 R19_2.1 | length 847
  Top w15: v1(6040,7470) 6087.2,7470 R19_2.1@6088.5,7468.7
  Inner Top w15: C18_2.1@5948.43,6710 6040,6801.57 v1(6040,7470)
NetC18_2_2: C18_2.2 J6_2.2 R27_2.1 | length 549.1
  Inner Top w15: C18_2.2@5751.57,6710 5850,6808.43 J6_2.2@5850,6990 5850,7085 v1(5915,7150)
  Bottom w15: R27_2.1@5873.62,7150 v1(5915,7150)
NetC20_1_1: C20_1.1 C25_1.2 R21_1.2 U6_1.1 | length 388.2
  Inner Top w15: C25_1.2@5751.57,4750 5811.57,4690 v1(5915,4690)
  Bottom w15: U6_1.1@5888.39,4842.4 5888.39,4798.39 5873.62,4783.62 R21_1.2@5873.62,4750 C20_1.1@5873.62,4690 v1(5915,4690)
NetC20_1_2: C20_1.2 R21_1.1 R27_1.2 U6_1.2 | length 227.5
  Bottom w15: R27_1.2@5826.38,4630 R21_1.1@5826.38,4750 5826.38,4776.38 5862.8,4812.8 U6_1.2@5862.8,4842.4
NetC20_2_1: C20_2.1 C25_2.2 R21_2.2 U6_2.1 | length 388.2
  Inner Top w15: C25_2.2@5751.57,7270 5811.57,7210 v1(5915,7210)
  Bottom w15: U6_2.1@5888.39,7362.4 5888.39,7318.39 5873.62,7303.62 R21_2.2@5873.62,7270 C20_2.1@5873.62,7210 v1(5915,7210)
NetC20_2_2: C20_2.2 R21_2.1 R27_2.2 U6_2.2 | length 227.5
  Bottom w15: R27_2.2@5826.38,7150 R21_2.1@5826.38,7270 5826.38,7296.38 5862.8,7332.8 U6_2.2@5862.8,7362.4
NetC22_1_1: C22_1.1 R24_1.2 U5_1.3 | length 497.9
  Top w15: U5_1.3@5475,4262.72 5475,4205 v1(5500,4180)
  Inner Top w15: C22_1.1@5178.43,4190 5227.64,4190 5237.64,4180 v1(5500,4180)
  Bottom w15: C22_1.1@5178.43,4190 5178.43,4266.93 R24_1.2@5180,4268.5
NetC22_1_2: C22_1.2 R29_1.2 | length 327.9
  Inner Top w15: R29_1.2@4686.85,4270 4736.85,4220 4951.57,4220 C22_1.2@4981.57,4190
NetC22_2_1: C22_2.1 R24_2.2 U5_2.3 | length 497.9
  Top w15: U5_2.3@5475,6782.72 5475,6725 v1(5500,6700)
  Inner Top w15: C22_2.1@5178.43,6710 5227.64,6710 5237.64,6700 v1(5500,6700)
  Bottom w15: C22_2.1@5178.43,6710 5178.43,6786.93 R24_2.2@5180,6788.5
NetC22_2_2: C22_2.2 R29_2.2 | length 327.9
  Inner Top w15: R29_2.2@4686.85,6790 4736.85,6740 4951.57,6740 C22_2.2@4981.57,6710
NetC24_1_1: C24_1.1 R20_1.2 R29_1.3 | length 453.9
  Inner Bottom w15: v1(4645,4435) 4611.02,4401.02 4610,4401.02 4610,4250 4686.85,4173.15 R29_1.3@4686.85,4171.57
  Bottom w15: C24_1.1@4610,4508.5 4645,4508.5 ; v1(4645,4435) 4645,4508.5 ; R20_1.2@4680,4508.5 4645,4508.5
NetC24_2_1: C24_2.1 R20_2.2 R29_2.3 | length 453.9
  Inner Bottom w15: v1(4645,6955) 4611.02,6921.02 4610,6921.02 4610,6770 4686.85,6693.15 R29_2.3@4686.85,6691.57
  Bottom w15: C24_2.1@4610,7028.5 4645,7028.5 ; v1(4645,6955) 4645,7028.5 ; R20_2.2@4680,7028.5 4645,7028.5
NetC25_1_1: C25_1.1 R26_1.1 | length 367
  Top w15: v1(6040,5030) 6087.2,5030 R26_1.1@6088.5,5028.7
  Inner Top w15: C25_1.1@5948.43,4750 5948.43,4938.43 v1(6040,5030)
NetC25_2_1: C25_2.1 R26_2.1 | length 367
  Top w15: v1(6040,7550) 6087.2,7550 R26_2.1@6088.5,7548.7
  Inner Top w15: C25_2.1@5948.43,7270 5948.43,7458.43 v1(6040,7550)
NetC27_1_1: C27_1.1 J6_1.3 J7_1.3 R22_1.2 U7_1.7 | length 2064.4
  Top w15: C27_1.1@5351.57,5760 5351.57,5608.43 5371.5,5588.5 R22_1.2@5400,5588.5 5400,5550 5425,5525 U7_1.7@5425,5497.28
  Inner Top w15: C27_1.1@5351.57,5760 5411.57,5700 5640,5700 J7_1.3@5950,5390
  Inner Bottom w15: J6_1.3@5950,4470 5850,4570 5850,5280 5850,5290 J7_1.3@5950,5390
NetC27_1_2: C27_1.2 R34_1.2 U7_1.6 | length 309.8
  Top w15: U7_1.6@5475,5497.28 5475,5525 5500,5550 R34_1.2@5500,5588.5 5528.5,5588.5 5548.43,5608.43 C27_1.2@5548.43,5760
NetC27_2_1: C27_2.1 J6_2.3 J7_2.3 R22_2.2 U7_2.7 | length 2064.4
  Top w15: C27_2.1@5351.57,8280 5351.57,8128.43 5371.5,8108.5 R22_2.2@5400,8108.5 5400,8070 5425,8045 U7_2.7@5425,8017.28
  Inner Top w15: C27_2.1@5351.57,8280 5411.57,8220 5640,8220 J7_2.3@5950,7910
  Inner Bottom w15: J6_2.3@5950,6990 5850,7090 5850,7800 5850,7810 J7_2.3@5950,7910
NetC27_2_2: C27_2.2 R34_2.2 U7_2.6 | length 309.8
  Top w15: U7_2.6@5475,8017.28 5475,8045 5500,8070 R34_2.2@5500,8108.5 5528.5,8108.5 5548.43,8128.43 C27_2.2@5548.43,8280
NetC31_1_1: C31_1.1 C32_1.2 R38_1.2 U6_1.7 | length 844.7
  Inner Top w15: C32_1.2@5751.57,5670 6010,5411.57 6010,5265 v1(5915,5170)
  Bottom w15: U6_1.7@5862.8,5017.6 5862.8,5062.8 5873.62,5073.62 R38_1.2@5873.62,5110 C31_1.1@5873.62,5170 v1(5915,5170)
NetC31_1_2: C31_1.2 R38_1.1 R39_1.2 U6_1.6 | length 216.9
  Bottom w15: R39_1.2@5826.38,5230 R38_1.1@5826.38,5110 5826.38,5073.62 5837.2,5062.8 U6_1.6@5837.2,5017.6
NetC31_2_1: C31_2.1 C32_2.2 R38_2.2 U6_2.7 | length 844.7
  Inner Top w15: C32_2.2@5751.57,8190 6010,7931.57 6010,7785 v1(5915,7690)
  Bottom w15: U6_2.7@5862.8,7537.6 5862.8,7582.8 5873.62,7593.62 R38_2.2@5873.62,7630 C31_2.1@5873.62,7690 v1(5915,7690)
NetC31_2_2: C31_2.2 R38_2.1 R39_2.2 U6_2.6 | length 216.9
  Bottom w15: R39_2.2@5826.38,7750 R38_2.1@5826.38,7630 5826.38,7593.62 5837.2,7582.8 U6_2.6@5837.2,7537.6
NetC32_1_1: C32_1.1 R36_1.1 | length 527
  Top w15: v1(6040,5230) 6087.2,5230 R36_1.1@6088.5,5228.7
  Inner Top w15: C32_1.1@5948.43,5670 6040,5578.43 v1(6040,5230)
NetC32_2_1: C32_2.1 R36_2.1 | length 527
  Top w15: v1(6040,7750) 6087.2,7750 R36_2.1@6088.5,7748.7
  Inner Top w15: C32_2.1@5948.43,8190 6040,8098.43 v1(6040,7750)
NetC33_1_1: C33_1.1 C34_1.1 R22_1.1 R34_1.1 R35_1.2 | length 1068.1
  Top w15: C34_1.1@5351.57,4850 C33_1.1@5351.57,4980 5380,4980 5401.5,5001.5 R35_1.2@5401.5,5090 ; R22_1.1@5410,5651.5 R34_1.1@5490,5651.5
  Inner Top w15: C33_1.1@5351.57,4980 5450,5078.43 v1(5450,5650)
NetC33_2_1: C33_2.1 C34_2.1 R22_2.1 R34_2.1 R35_2.2 | length 1068.1
  Top w15: C34_2.1@5351.57,7370 C33_2.1@5351.57,7500 5380,7500 5401.5,7521.5 R35_2.2@5401.5,7610 ; R22_2.1@5410,8171.5 R34_2.1@5490,8171.5
  Inner Top w15: C33_2.1@5351.57,7500 5450,7598.43 v1(5450,8170)
NetC35_1_1: C35_1.1 R41_1.2 U5_1.5 | length 576.6
  Top w15: U5_1.5@5527.72,4480 U5_1.5@5525,4477.28 5525,4535 v1(5550,4560)
  Inner Top w15: C35_1.1@5178.43,4550 5260,4550 5290,4520 5510,4520 v1(5550,4560)
  Bottom w15: C35_1.1@5178.43,4550 5178.43,4473.07 R41_1.2@5180,4471.5
NetC35_1_2: C35_1.2 R29_1.2' | length 452.9
  Inner Top w15: R29_1.2'@4785.28,4270 4880,4270 4900,4290 4900,4530 4920,4550 C35_1.2@4981.57,4550
NetC35_2_1: C35_2.1 R41_2.2 U5_2.5 | length 576.6
  Top w15: U5_2.5@5527.72,7000 U5_2.5@5525,6997.28 5525,7055 v1(5550,7080)
  Inner Top w15: C35_2.1@5178.43,7070 5260,7070 5290,7040 5510,7040 v1(5550,7080)
  Bottom w15: C35_2.1@5178.43,7070 5178.43,6993.07 R41_2.2@5180,6991.5
NetC35_2_2: C35_2.2 R29_2.2' | length 452.9
  Inner Top w15: R29_2.2'@4785.28,6790 4880,6790 4900,6810 4900,7050 4920,7070 C35_2.2@4981.57,7070
NetC38_1_1: C38_1.1 R29_1.3' R37_1.2 | length 452.4
  Inner Bottom w15: R29_1.3'@4785.28,4171.57 4860,4246.3 4860,4400 v1(4825,4435)
  Bottom w15: R37_1.2@4790,4508.5 4825,4508.5 ; v1(4825,4435) 4825,4508.5 ; C38_1.1@4860,4508.5 4825,4508.5
NetC38_2_1: C38_2.1 R29_2.3' R37_2.2 | length 452.4
  Inner Bottom w15: R29_2.3'@4785.28,6691.57 4860,6766.3 4860,6920 v1(4825,6955)
  Bottom w15: R37_2.2@4790,7028.5 4825,7028.5 ; v1(4825,6955) 4825,7028.5 ; C38_2.1@4860,7028.5 4825,7028.5
NetC39_1_1: C39_1.1 R42_1.1 | length 158.8
  Top w15: C39_1.1@5948.43,5110 C39_1.1@5950,5110 ; v1(6040,5150) 6087.2,5150 R42_1.1@6088.5,5148.7
  Inner Top w15: C39_1.1@5948.43,5110 6000,5110 v1(6040,5150)
NetC39_1_2: C39_1.2 J7_1.2 R39_1.1 | length 449.1
  Inner Top w15: C39_1.2@5751.57,5110 5751.57,5196.57 5850,5295 ; J7_1.2@5850,5390 5850,5295 ; v1(5915,5230) 5850,5295
  Bottom w15: R39_1.1@5873.62,5230 v1@5910,5230
NetC39_2_1: C39_2.1 R42_2.1 | length 158.8
  Top w15: C39_2.1@5948.43,7630 C39_2.1@5950,7630 ; v1(6040,7670) 6087.2,7670 R42_2.1@6088.5,7668.7
  Inner Top w15: C39_2.1@5948.43,7630 6000,7630 v1(6040,7670)
NetC39_2_2: C39_2.2 J7_2.2 R39_2.1 | length 449.1
  Inner Top w15: C39_2.2@5751.57,7630 5751.57,7716.57 5850,7815 ; J7_2.2@5850,7910 5850,7815 ; v1(5915,7750) 5850,7815
  Bottom w15: R39_2.1@5873.62,7750 v1@5910,7750
NetC41_1_1: C41_1.1 C56_1.1 C57_1.1 J9_1.1 J9_1.2 J10_1.1 L5_1.2 | length 163.8
  Bottom w25: C57_1.1@9140,3938.5 C41_1.1@9220,3938.5 C56_1.1@9220,3854.72
  other v1: 8730,3780 8770,3780 8730,3820 8770,3820 8730,3860 8770,3860 8730,3900 8770,3900 8730,3940 8770,3940 11570,3950 11610,3950 12090,3950 12130,3950 11570,3990 11610,3990 12090,3990 12130,3990 8500,4020 8540,4020 8580,4020 8620,4020 8660,4020 11570,4030 11610,4030 12090,4030 12130,4030 8500,4060 8540,4060 8580,4060 8620,4060 8660,4060 11570,4070 11610,4070 12090,4070 12130,4070 11570,4110 11610,4110 12090,4110 12130,4110
NetC41_1_2: C41_1.2 R45_1.2 | length 80
  Bottom w25: C41_1.2@9220,4001.5 R45_1.2@9300,4001.5
NetC41_2_1: C41_2.1 C56_2.1 C57_2.1 J9_2.1 J9_2.2 J10_2.1 L5_2.2 | length 163.8
  Bottom w25: C57_2.1@9140,6458.5 C41_2.1@9220,6458.5 C56_2.1@9220,6374.72
  other v1: 8730,6300 8770,6300 8730,6340 8770,6340 8730,6380 8770,6380 8730,6420 8770,6420 8730,6460 8770,6460 11570,6470 11610,6470 12090,6470 12130,6470 11570,6510 11610,6510 12090,6510 12130,6510 8500,6540 8540,6540 8580,6540 8620,6540 8660,6540 11570,6550 11610,6550 12090,6550 12130,6550 8500,6580 8540,6580 8580,6580 8620,6580 8660,6580 11570,6590 11610,6590 12090,6590 12130,6590 11570,6630 11610,6630 12090,6630 12130,6630
NetC41_2_2: C41_2.2 R45_2.2 | length 80
  Bottom w25: C41_2.2@9220,6521.5 R45_2.2@9300,6521.5
NetC54_1_1: C54_1.1 U8_1.43 | length 268.5
  Top w15: v1(7010,4545) 7010,4610 v1(7050,4650)
  Bottom w15: U8_1.43@6979.61,4692.5 7007.5,4692.5 v1(7050,4650) ; C54_1.1@6988.5,4495 6988.5,4523.5 v1(7010,4545)
NetC54_1_2: C54_1.2 L6_1.2 U8_1.35 | length 576.3
  Top w15: v1(7050,4453.7) 6980,4523.7 6980,4873.7 7000,4893.7 v1(7050,4893.7)
  Bottom w15: v1(7050,4453.7) 7050,4498.5 C54_1.2@7051.5,4500 ; C54_1.2@7060,4505.2 C54_1.2@7061.5,4503.7
  other v1: 8120,4440 8160,4440 8120,4480 8160,4480 8120,4520 8160,4520 8120,4560 8160,4560 9780,4560 9820,4560 9860,4560 9900,4560 9940,4560 8120,4600 8160,4600 9780,4600 9820,4600 9860,4600 9900,4600 9940,4600 8120,4640 8160,4640 8120,4680 8160,4680 9670,4680 9710,4680 8120,4720 8160,4720 9670,4720 9710,4720 8120,4760 8160,4760 9670,4760 9710,4760 8120,4800 8160,4800 9670,4800 9710,4800 9670,4840 9710,4840 7080,4895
